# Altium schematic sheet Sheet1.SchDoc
size A4
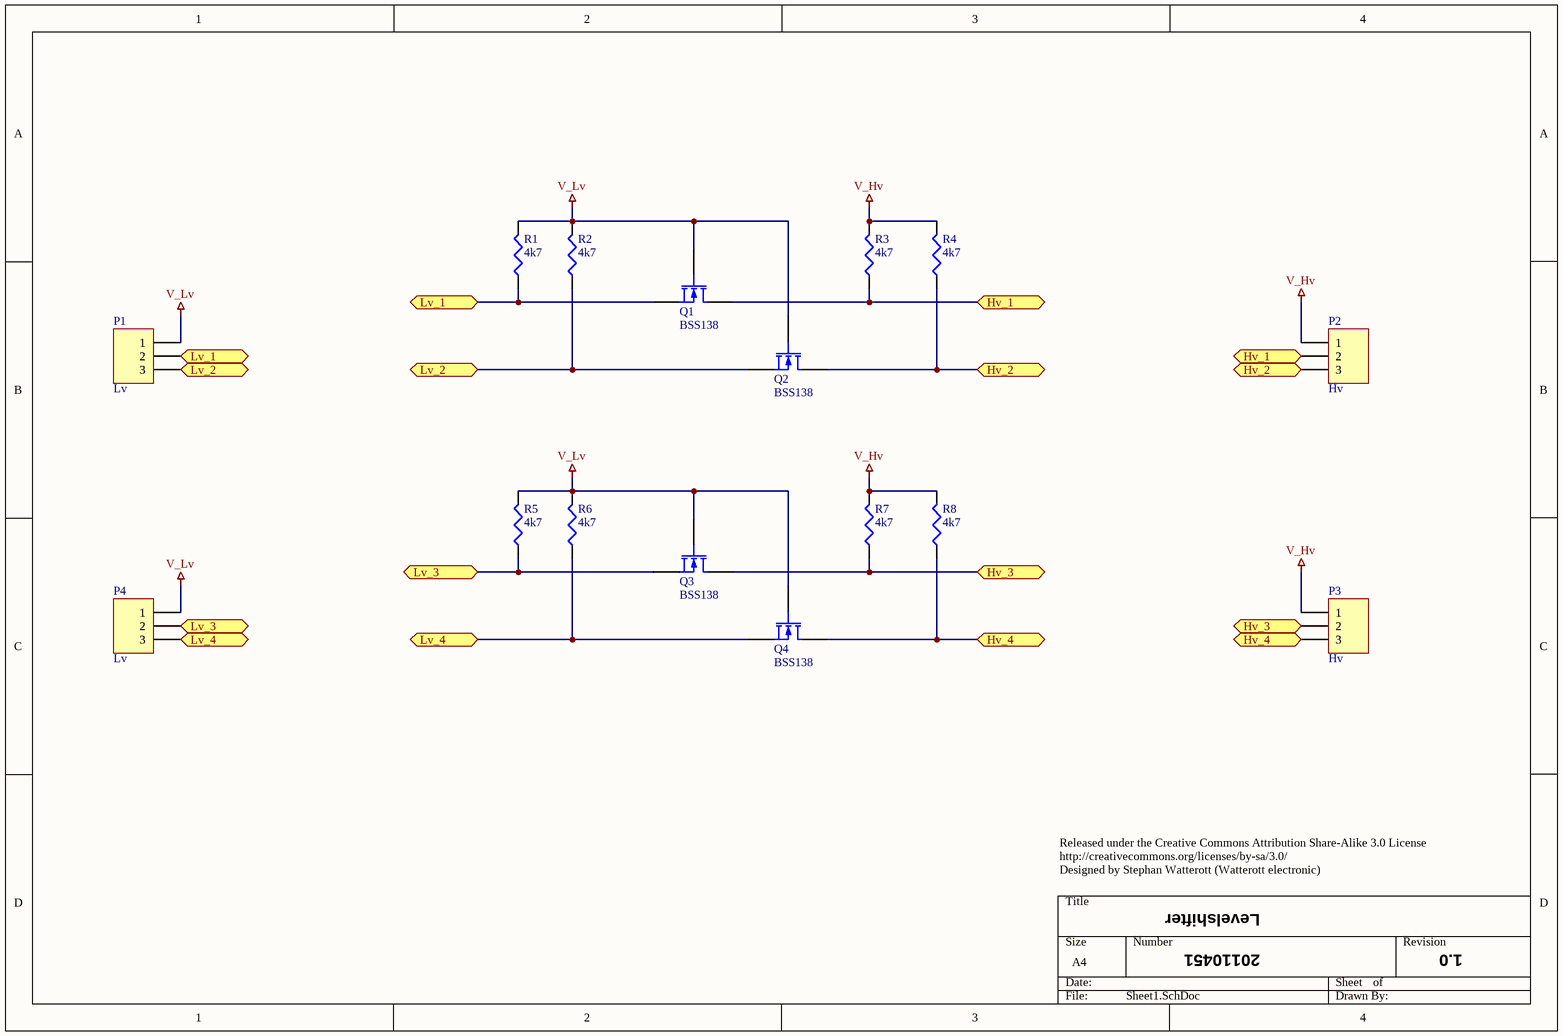
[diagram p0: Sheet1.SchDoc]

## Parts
P1  Lv  [HDR1X3]
P2  Hv  [HDR1X3]
P3  Hv  [HDR1X3]
P4  Lv  [HDR1X3]
Q1  BSS138  [SOT23]
Q2  BSS138  [SOT23]
Q3  BSS138  [SOT23]
Q4  BSS138  [SOT23]
R1  4k7  [J1-0603]
R2  4k7  [J1-0603]
R3  4k7  [J1-0603]
R4  4k7  [J1-0603]
R5  4k7  [J1-0603]
R6  4k7  [J1-0603]
R7  4k7  [J1-0603]
R8  4k7  [J1-0603]

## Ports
Hv_1, Hv_2, Hv_3, Hv_4, Lv_1, Lv_2, Lv_3, Lv_4

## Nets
V_Hv: P2.1 P3.1 R3.2 R4.2 R7.2 R8.2
V_Lv: P1.1 P4.1 Q1.3(G) Q2.3(G) Q3.3(G) Q4.3(G) R1.2 R2.2 R5.2 R6.2
Hv_1: P2.2 Q1.1(D) R3.1 ; port Hv_1
Hv_2: P2.3 Q2.1(D) R4.1 ; port Hv_2
Hv_3: P3.2 Q3.1(D) R7.1 ; port Hv_3
Hv_4: P3.3 Q4.1(D) R8.1 ; port Hv_4
Lv_1: P1.2 Q1.2(S) R1.1 ; port Lv_1
Lv_2: P1.3 Q2.2(S) R2.1 ; port Lv_2
Lv_3: P4.2 Q3.2(S) R5.1 ; port Lv_3
Lv_4: P4.3 Q4.2(S) R6.1 ; port Lv_4

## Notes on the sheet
- Released under the Creative Commons Attribution Share-Alike 3.0 License
  http://creativecommons.org/licenses/by-sa/3.0/
  Designed by Stephan Watterott (Watterott electronic)
- Levelshifter
- 20110451
- 1.0

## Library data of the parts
P1-P4 = Header 3: Header, 3-Pin
Q1-Q4 = BSS138: N-Channel Enhancement Mode Vertical DMOS FET
R1-R8 = Res3: Resistor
